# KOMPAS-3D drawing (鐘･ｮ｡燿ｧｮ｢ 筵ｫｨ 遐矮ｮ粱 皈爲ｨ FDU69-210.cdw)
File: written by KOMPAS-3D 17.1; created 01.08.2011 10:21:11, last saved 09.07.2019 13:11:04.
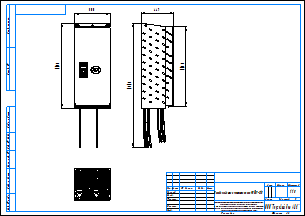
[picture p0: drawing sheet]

Title block, sheet 1: name: Преобразователи частоты серии FDU69-210; scale: 1:10; sheets: 1; sheet format: A3; stored path: \\adlc.lan\data\АДЛ_ПКД\3D-модели\Поставщики\Оборудование Emotron\Преобразователи частоты\Серия FDU 2.0\KOMPAS 2D\Преобразователи частоты серии FDU69-210.cdw

Views: Спереди 1
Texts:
  Рама для чертежей
  Лит-Масса-Масштаб
  Материал-Предприятие
  Масштаб
  Изм.
  Лист
  № докум.
  Подп.
  Дата
  Лит.
  Разраб.
  Пров.
  Т.контр.
  Листов
  Внимание! Данный продукт является объектом авторского права ООО «Торговый Дом АДЛ».
  Запрещается изменение, копирование, распространение
  (в том числе путем копирования на другие сайты и ресурсы в Интернете)
  или любое иное использование информации и объектов без предварительного
  согласия правообладателя (ООО «Торговый Дом АДЛ»).
  Н.контр.
  Утв.
  ООО "Торговый дом АДЛ"
  Изменение
  Номер документа
  Подпись
  Обозначение документа
  Наименование изделия
  Масса изделия по ГОСТ 2.109-73
  Порядковый номер листа
  Общее количество листов в документе
  Характер работы, выполненной лицом, подписавшим документ
  Наименование или индекс предприятия, выпускающего документ
  Инв. № подл.
  Подп. и дата
  Взам. инв. №
  Инв. № дубл.
  Инвентарный номер подлинника по ГОСТ 2.501-68
  Подпись принявшего подлинник в отдел технической документации
  Инвентарный номер подлинника, взамен которого выпущен данный подлинник
  Инвентарный номер дубликата по ГОСТ 2.502-68
  Подпись принявшего дубликат в отдел технической документации
  Справ. №
  Перв. примен.
  Обозначение документа, взамен или на основании которого выпущен данный документ
  Обозначение документа, в котором впервые записан данный документ
  Подпись лица, копировавшего чертеж
  Обозначение формата листа
  !Рама для чертежа
Dimensions and other numbers on the sheet: 1176; 500; 449; 1718; 1100; 1:10; 1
